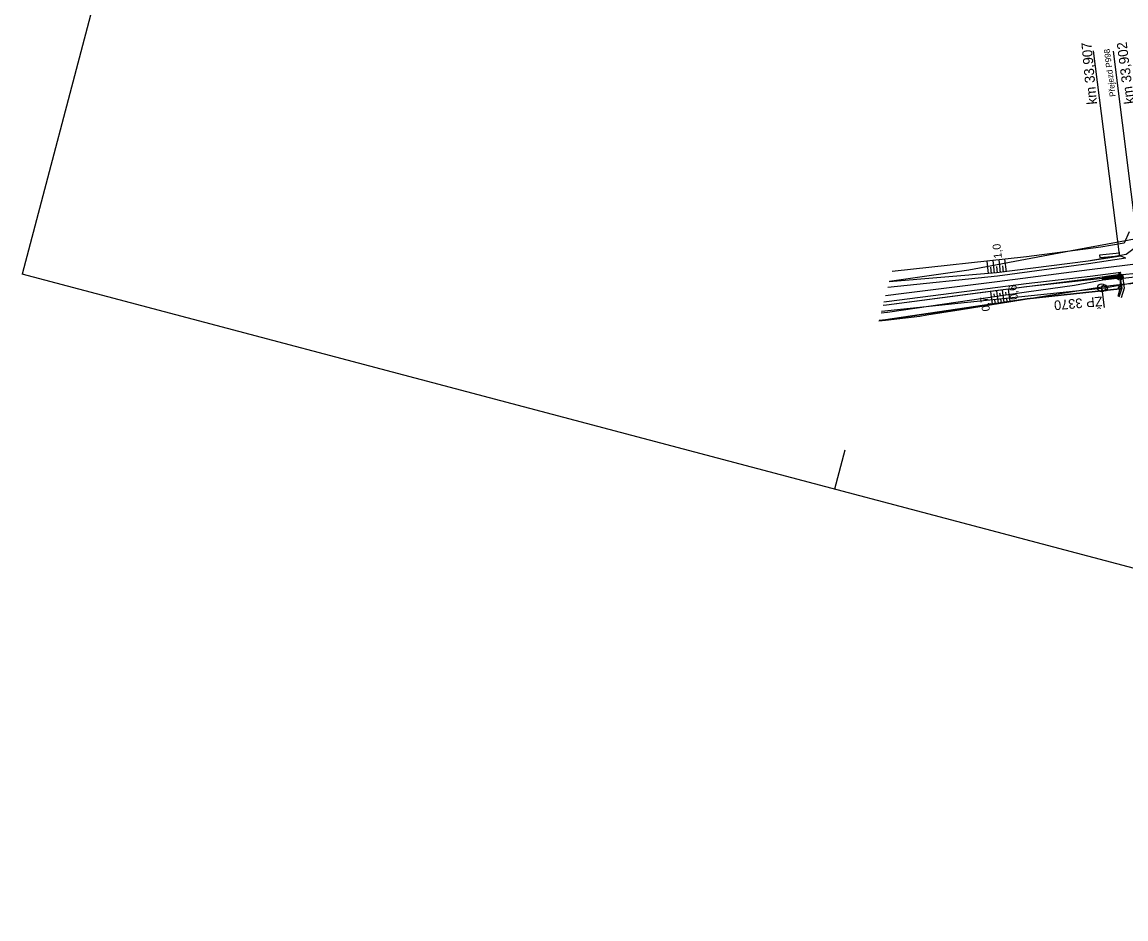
# Model space of a CAD drawing. Extents: x -805011 to -803920, y -1150790 to -1150234.
# Drawn here: x -805011.3 to -804735.5, y -1150682.7 to -1150458.6 of the extents above; entities that cross this region are included whole.
import ezdxf

# ---------------------------------------------------------------- set-up
doc = ezdxf.new("R2010")
doc.units = 0
for name, color, linetype in [('0381KM032-037P - Vrstva 1', 7, 'Continuous'), ('0381KM032-037P - Vrstva 13', 7, 'Continuous'), ('0381KM032-037P - Vrstva 17', 7, 'Continuous'), ('0381KM032-037P - Vrstva 25', 7, 'Continuous'), ('0381KM032-037P - Vrstva 36', 7, 'Continuous'), ('0381KM032-037P - Vrstva 4', 7, 'Continuous'), ('0381KM032-037P - Vrstva 43', 7, 'Continuous'), ('0381KM032-037P - Vrstva 48', 7, 'Continuous'), ('0381KM032-037P - Vrstva 49', 7, 'Continuous'), ('0381KM032-037P - Vrstva 51', 7, 'Continuous'), ('0381KM032-037P - Vrstva 9', 7, 'Continuous'), ('formát', 7, 'Continuous'), ('hran DP - hran DP', 7, 'Continuous'), ('vyt_sit - polygon', 7, 'Continuous'), ('vyt_sit - stávající', 7, 'Continuous')]:
    doc.layers.add(name, color=color, linetype=linetype)

msp = doc.modelspace()

# ---------------------------------------------------------------- linework, layer by layer
at = {"layer": '0381KM032-037P - Vrstva 1'}
for points in [[(-804485.9, -1150487.74), (-804508.11, -1150490.55), (-804529.67, -1150493.3), (-804537.63, -1150494.31), (-804546.61, -1150495.46), (-804554.2, -1150496.42), (-804564.05, -1150497.67), (-804586.01, -1150500.48), (-804607.92, -1150503.26), (-804630.35, -1150506.11), (-804652.65, -1150508.9), (-804675.7, -1150511.78), (-804698.85, -1150514.71), (-804701.61, -1150515.06), (-804722.18, -1150517.67), (-804729.05, -1150518.54), (-804735.1, -1150519.31), (-804744.56, -1150520.5), (-804767.65, -1150523.46), (-804791, -1150526.42)], [(-804791, -1150526.42), (-804795.53, -1150527)]]:
    msp.add_lwpolyline(points, dxfattribs=at)
at = {"layer": '0381KM032-037P - Vrstva 13'}
msp.add_line((-804736.93, -1150522.56), (-804736.22, -1150522.62), dxfattribs=at)
for points in [[(-804736.32, -1150521.88), (-804741.33, -1150522.48), (-804741.32, -1150522.62), (-804736.39, -1150522.04)], [(-804736.33, -1150522.27), (-804741.29, -1150522.87), (-804741.32, -1150522.62)], [(-804741.29, -1150522.87), (-804741.28, -1150522.98), (-804736.24, -1150522.43)], [(-804736.93, -1150522.56), (-804736.54, -1150525.1), (-804737.22, -1150527.34)], [(-804736.22, -1150522.62), (-804735.92, -1150525.05), (-804736.64, -1150527.49)], [(-804736.32, -1150521.88), (-804736.39, -1150522.04), (-804736.33, -1150522.27), (-804736.24, -1150522.43)]]:
    msp.add_lwpolyline(points, dxfattribs=at)
at = {"layer": '0381KM032-037P - Vrstva 17'}
for points in [[(-804734.71, -1150510.96), (-804735.96, -1150513.84), (-804741.77, -1150514.83), (-804760.36, -1150517.2), (-804793.92, -1150520.9)], [(-804797.16, -1150533.15), (-804795.6, -1150532.98), (-804760.14, -1150527.72), (-804737.02, -1150525.24), (-804737.52, -1150527.15)]]:
    msp.add_lwpolyline(points, dxfattribs=at)
at = {"layer": '0381KM032-037P - Vrstva 25'}
for p, q in [((-804737.43, -1150521.73), (-804736.43, -1150522.84)), ((-804737.41, -1150522.86), (-804736.43, -1150521.74)), ((-804736.93, -1150523.04), (-804736.93, -1150524.54)), ((-804737.32, -1150525.02), (-804736.85, -1150524.55)), ((-804737.06, -1150525.32), (-804736.56, -1150524.82))]:
    msp.add_line(p, q, dxfattribs=at)
for centre, radius in [((-804736.94, -1150522.29), 0.749), ((-804736.93, -1150524.94), 0.4), ((-804736.93, -1150524.94), 0.4)]:
    msp.add_circle(centre, radius, dxfattribs=at)
at = {"layer": '0381KM032-037P - Vrstva 36'}
for p, q in [((-804741.54, -1150524.95), (-804741.54, -1150524.95)), ((-804741.41, -1150525.95), (-804740.91, -1150529.91))]:
    msp.add_line(p, q, dxfattribs=at)
msp.add_circle((-804741.54, -1150524.95), 1, dxfattribs=at)
at = {"layer": '0381KM032-037P - Vrstva 4'}
msp.add_line((-804738.68, -1150465.82), (-804731.99, -1150518.9), dxfattribs=at)
for points in [[(-804735.49, -1150517.59), (-804736.73, -1150517.05), (-804744.9, -1150518.34), (-804767.83, -1150521.26)], [(-804735.49, -1150517.59), (-804744.82, -1150519), (-804767.55, -1150522.1)], [(-804767.55, -1150522.1), (-804794.99, -1150524.93)], [(-804767.83, -1150521.26), (-804794.61, -1150523.51)], [(-804736.74, -1150521.15), (-804737.38, -1150521.73), (-804744.34, -1150522.73), (-804767.48, -1150525.67)], [(-804736.74, -1150521.15), (-804744.39, -1150522.13), (-804760.4, -1150524), (-804767.46, -1150524.91)], [(-804767.48, -1150525.67), (-804795.35, -1150529.3), (-804796.17, -1150529.4)], [(-804767.46, -1150524.91), (-804795.31, -1150528.51), (-804795.96, -1150528.6)]]:
    msp.add_lwpolyline(points, dxfattribs=at)
at = {"layer": '0381KM032-037P - Vrstva 43'}
msp.add_lwpolyline([(-804736.33, -1150521.65), (-804729.5, -1150520.98), (-804729.45, -1150521.92), (-804736.22, -1150522.62)], close=True, dxfattribs=at)
at = {"layer": '0381KM032-037P - Vrstva 48'}
for p, q in [((-804769.83, -1150521.43), (-804770.13, -1150518.28)), ((-804769.08, -1150521.37), (-804769.23, -1150519.78)), ((-804768.33, -1150521.3), (-804768.64, -1150518.12)), ((-804767.55, -1150521.23), (-804767.74, -1150519.63)), ((-804766.81, -1150521.13), (-804767.19, -1150517.96)), ((-804766.07, -1150521.04), (-804766.25, -1150519.46)), ((-804765.32, -1150520.94), (-804765.7, -1150517.79)), ((-804769.09, -1150527.24), (-804769.27, -1150525.92)), ((-804767.6, -1150527.03), (-804767.78, -1150525.73)), ((-804766.12, -1150526.81), (-804766.3, -1150525.53)), ((-804764.64, -1150526.59), (-804764.81, -1150525.34)), ((-804768.83, -1150529.01), (-804769.09, -1150527.24)), ((-804768.35, -1150527.13), (-804768.44, -1150526.48)), ((-804768.09, -1150528.9), (-804768.22, -1150528.02)), ((-804767.35, -1150528.79), (-804767.61, -1150527.03)), ((-804766.86, -1150526.92), (-804766.95, -1150526.27)), ((-804766.61, -1150528.68), (-804766.74, -1150527.8)), ((-804765.87, -1150528.57), (-804766.12, -1150526.81)), ((-804765.38, -1150526.7), (-804765.46, -1150526.07)), ((-804765.12, -1150528.46), (-804765.25, -1150527.58)), ((-804764.38, -1150528.35), (-804764.64, -1150526.59))]:
    msp.add_line(p, q, dxfattribs=at)
at = {"layer": '0381KM032-037P - Vrstva 49'}
for points in [[(-804731.33, -1150510.42), (-804733.06, -1150514.89), (-804735.43, -1150516.61), (-804744.9, -1150518.34), (-804767.83, -1150521.26), (-804794.61, -1150523.51)], [(-804735.96, -1150513.84), (-804741.77, -1150514.83), (-804760.36, -1150517.2), (-804793.92, -1150520.9)], [(-804796.66, -1150531.24), (-804795.08, -1150531.02), (-804760.31, -1150525.97), (-804748.35, -1150524.3), (-804741.28, -1150522.98)], [(-804741.32, -1150522.62), (-804760.31, -1150524.76), (-804795.35, -1150529.3), (-804796.17, -1150529.4)], [(-804741.32, -1150522.62), (-804741.29, -1150522.87), (-804741.28, -1150522.98)], [(-804737.02, -1150525.24), (-804760.14, -1150527.72), (-804795.6, -1150532.98), (-804797.16, -1150533.15)]]:
    msp.add_lwpolyline(points, dxfattribs=at)
at = {"layer": '0381KM032-037P - Vrstva 51'}
msp.add_lwpolyline([(-804736.22, -1150522.62), (-804735.92, -1150525.05), (-804736.64, -1150527.49)], dxfattribs=at)
at = {"layer": '0381KM032-037P - Vrstva 9'}
for p, q in [((-804737.08, -1150516.65), (-804743.56, -1150465.71)), ((-804737.11, -1150516.35), (-804742.09, -1150516.81)), ((-804742.09, -1150516.81), (-804742.04, -1150517.41)), ((-804742.04, -1150517.41), (-804737.06, -1150516.95)), ((-804737.11, -1150516.35), (-804737.17, -1150515.76)), ((-804737.06, -1150516.95), (-804737.11, -1150516.35))]:
    msp.add_line(p, q, dxfattribs=at)
at = {"layer": 'formát'}
for p, q in [((-804935.34, -1150234.42), (-805011.32, -1150521.54)), ((-804402.28, -1150682.7), (-805011.32, -1150521.54)), ((-804805.75, -1150565.59), (-804808.3, -1150575.26))]:
    msp.add_line(p, q, dxfattribs=at)
at = {"layer": 'hran DP - hran DP'}
for p, q in [((-804747.72, -1150515.43), (-804723.03, -1150510.78)), ((-804774.72, -1150520.52), (-804747.72, -1150515.43)), ((-804794.57, -1150523.35), (-804774.72, -1150520.52)), ((-804744.2, -1150525.25), (-804766.8, -1150528.89)), ((-804739.31, -1150524.46), (-804744.2, -1150525.25)), ((-804736.36, -1150524.18), (-804739.31, -1150524.46)), ((-804729.97, -1150523.63), (-804736.36, -1150524.18)), ((-804776.65, -1150530.47), (-804785.22, -1150531.85)), ((-804766.8, -1150528.89), (-804776.65, -1150530.47)), ((-804795.52, -1150533.13), (-804797.21, -1150533.33)), ((-804786.96, -1150532.13), (-804795.52, -1150533.13)), ((-804785.22, -1150531.85), (-804786.96, -1150532.13))]:
    msp.add_line(p, q, dxfattribs=at)
at = {"layer": 'vyt_sit - polygon'}
for p, q in [((-804740.83, -1150524.99), (-804594.75, -1150498.6)), ((-804796.54, -1150530.81), (-804740.83, -1150524.99))]:
    msp.add_line(p, q, dxfattribs=at)
at = {"layer": 'vyt_sit - stávající'}
msp.add_line((-804740.89, -1150524.99), (-804740.79, -1150524.99), dxfattribs=at)
msp.add_circle((-804740.83, -1150524.99), 0.756, dxfattribs=at)

# ---------------------------------------------------------------- texts
at = {"layer": '0381KM032-037P - Vrstva 4'}
for s, height, p in [('km 33,902', 2.5, (-804733.36, -1150478.88)), ('Přejezd P998', 1.5, (-804738.02, -1150477.13))]:
    msp.add_text(s, height=height, rotation=97.1938, dxfattribs=at).set_placement(p)
at = {"layer": '0381KM032-037P - Vrstva 48'}
for s, rotation, p in [('1,0', 96.2855, (-804766.46, -1150517.56)), ('0,6', 97.4164, (-804762.42, -1150527.82)), ('0,7', 98.2601, (-804769.42, -1150530.71))]:
    msp.add_text(s, height=2, rotation=rotation, dxfattribs=at).set_placement(p)
at = {"layer": '0381KM032-037P - Vrstva 9'}
msp.add_text('km 33,907', height=2.5, rotation=95.2837, dxfattribs=at).set_placement((-804742.69, -1150479.05))
at = {"layer": 'vyt_sit - stávající'}
msp.add_text('ŽP 3370', height=2.4, rotation=185, dxfattribs=at).set_placement((-804741.45, -1150527.14))

doc.saveas('drawing.dxf')
